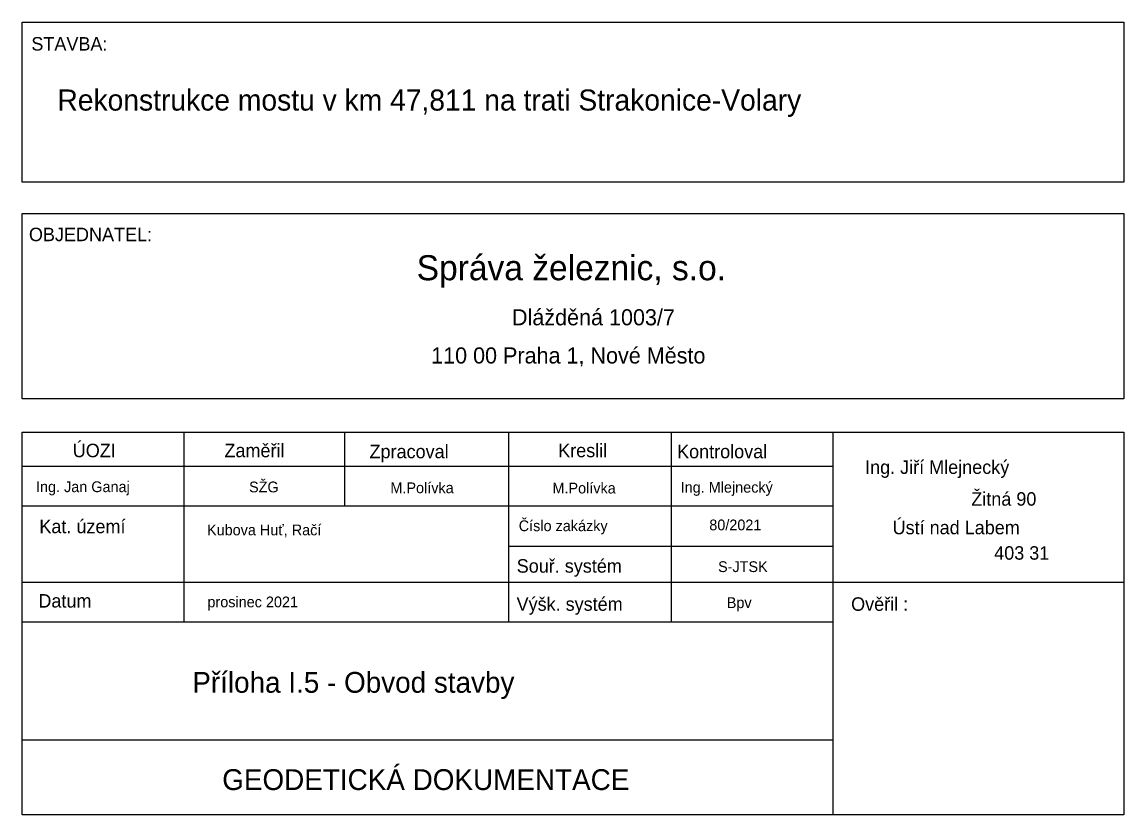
# Model space of a CAD drawing. Extents: x -879530 to -879371, y -1019242 to -1019127.
import ezdxf

# ---------------------------------------------------------------- set-up
doc = ezdxf.new("R2010")
doc.units = 0
doc.layers.add('tabulka', color=7, linetype='Continuous')

msp = doc.modelspace()

# ---------------------------------------------------------------- linework, layer by layer
at = {"layer": 'tabulka'}
for p, q in [((-879530.09, -1019186.45), (-879371.44, -1019186.45)), ((-879506.8, -1019186.45), (-879506.8, -1019213.77)), ((-879483.66, -1019186.45), (-879483.66, -1019197.07)), ((-879460.06, -1019186.45), (-879460.06, -1019213.77)), ((-879436.61, -1019186.45), (-879436.61, -1019213.77)), ((-879413.31, -1019241.58), (-879413.31, -1019186.45)), ((-879530.09, -1019191.36), (-879413.31, -1019191.36)), ((-879530.09, -1019197.07), (-879413.31, -1019197.07)), ((-879460.06, -1019202.88), (-879413.31, -1019202.88)), ((-879530.09, -1019208.07), (-879371.44, -1019208.07)), ((-879530.09, -1019213.77), (-879413.31, -1019213.77)), ((-879530.09, -1019230.76), (-879413.31, -1019230.76))]:
    msp.add_line(p, q, dxfattribs=at)
for points in [[(-879530.09, -1019127.36), (-879371.44, -1019127.36), (-879371.44, -1019150.43), (-879530.09, -1019150.43)], [(-879530.09, -1019154.95), (-879371.44, -1019154.95), (-879371.44, -1019181.64), (-879530.09, -1019181.64)]]:
    msp.add_lwpolyline(points, close=True, dxfattribs=at)
msp.add_lwpolyline([(-879371.44, -1019186.45), (-879371.44, -1019241.58), (-879530.09, -1019241.58), (-879530.09, -1019186.45)], dxfattribs=at)

# ---------------------------------------------------------------- texts
for s, height, p in [('STAVBA:', 1.94, (-879528.75, -1019131.47)), ('Rekonstrukce mostu v km 47,811 na trati Strakonice-Volary', 3.04, (-879525, -1019140.12)), ('OBJEDNATEL:', 1.94, (-879529.1, -1019158.93)), ('Správa železnic, s.o.', 3.61, (-879473.27, -1019164.56)), ('Dlážděná 1003/7', 2.32, (-879459.55, -1019171.05)), ('110 00 Praha 1, Nové Město', 2.32, (-879471.19, -1019176.55)), ('ÚOZI', 1.94, (-879522.79, -1019190.05)), ('Zaměřil', 1.94, (-879500.95, -1019190.05)), ('Zpracoval', 1.94, (-879480.06, -1019190.2)), ('Kreslil', 1.94, (-879452.9, -1019190.05)), ('Kontroloval', 1.94, (-879435.78, -1019190.2)), ('Ing. Jiří Mlejnecký', 1.94, (-879408.71, -1019192.45)), ('Ing. Jan Ganaj', 1.552, (-879528.08, -1019195.08)), ('SŽG', 1.552, (-879497.41, -1019195.11)), ('M.Polívka', 1.552, (-879477.05, -1019195.23)), ('M.Polívka', 1.552, (-879453.72, -1019195.27)), ('Ing. Mlejnecký', 1.552, (-879435.26, -1019195.15)), ('Žitná 90', 1.94, (-879393.42, -1019197.03)), ('Kat. území', 1.94, (-879527.6, -1019200.99)), ('Kubova Huť, Račí', 1.552, (-879503.46, -1019201.3)), ('Číslo zakázky', 1.552, (-879458.58, -1019200.7)), ('80/2021', 1.552, (-879431.14, -1019200.58)), ('Ústí nad Labem', 1.94, (-879404.75, -1019201.15)), ('403 31', 1.94, (-879390.12, -1019204.81)), ('Souř. systém', 1.94, (-879458.87, -1019206.68)), ('S-JTSK', 1.552, (-879429.88, -1019206.59)), ('Datum', 1.94, (-879527.74, -1019211.71)), ('prosinec 2021', 1.552, (-879503.4, -1019211.67)), ('Výšk. systém', 1.94, (-879458.89, -1019212.17)), ('Bpv', 1.552, (-879428.62, -1019211.78)), ('Ověřil :', 1.94, (-879410.72, -1019212.17)), ('Příloha I.5 - Obvod stavby', 3, (-879505.58, -1019223.98)), ('GEODETICKÁ DOKUMENTACE ', 3, (-879501.27, -1019237.99))]:
    msp.add_text(s, height=height, dxfattribs=at).set_placement(p)

doc.saveas('drawing.dxf')
